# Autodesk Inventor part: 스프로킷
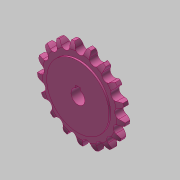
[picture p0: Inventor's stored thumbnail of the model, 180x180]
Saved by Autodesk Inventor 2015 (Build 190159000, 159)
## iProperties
Created: 2019-06
Part Number: 스프로킷
Material: 알루미늄 6061
Document SubType Name: Modeling
Designer: mduedu
Density: 1 g/cm^3
Appearance: 분홍색
Author: mduedu
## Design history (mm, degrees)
sketch "스케치1"
  geometry: L1 (0, 0)-(-3.6, 0); L2 (-3.6, 0)-(-3.6, 32.203); L3 (-2, 38)-(0, 38); L4 (0, 38)-(0, 0); L5 (0, 0)-(3.6, 0); L6 (3.6, 0)-(3.6, 32.203); L7 (2, 38)-(0, 38); A1 r 13.5 centre (9.887, 31.6) between (-2, 38) and (-3.6, 32.203); A2 r 13.5 centre (-9.887, 31.6) between (3.6, 32.203) and (2, 38)
  constraints: 14 end point, 4 point on circle, 4 symmetric about line, 2 centre point, 2 perpendicular, 1 horizontal, 1 parallel, 1 other
  dimensions: "d0" = 76 diameter of L3 L1; "d2" = 7.2 distance between parallel lines of L6 L2; "d3" = 1.6 distance from line of L3.start L2; "d4" = 6.4 distance from line of A2.centre L3; "d5" = 13.5 radius of A1
revolve "회전1" sketch "스케치1" stored, may be unused: angle "d6" = 90 deg
sketch "스케치2"
  geometry: L1 (34.56, 0)-(-34.56, 0); A1 r 34.56 centre (0, 0) between (34.56, 0) and (30.537, -16.182); A2 r 3.975 centre (34.56, 0) between (33.601, 3.858) and (33.601, -3.858); A3 r 12.7 centre (30.537, -16.182) between (37.583, -5.616) and (33.601, -3.858); A4 r 12.7 centre (30.537, 16.182) between (33.601, 3.858) and (37.583, 5.616); A5 r 38 centre (0, 0) between (37.583, -5.616) and (37.583, 5.616); 2 further points
  constraints: 11 point on circle, 5 centre point, 2 coincident, 2 end point, 2 symmetric about line, 1 horizontal, 1 horizontal alignment, 1 tangent, 3 other
  dimensions: "d7" = 69.12 diameter of A1; "d8" = 7.95 diameter of A2; "d9" = 12.7 radius of A3
extrude "돌출1" cut sketch "스케치2" stored distance "d10" = 10; taper "d11" = 0 deg
sketch "스케치3"
  geometry: C1 r 27 at (0, 0); 1 further point
  constraints: 1 centre point, 1 coincident
  dimensions: "d15" = 54 diameter of C1
extrude "돌출2" join sketch "스케치3" stored distance "d16" = 10; taper "d17" = 0 deg
sketch "스케치4"
  geometry: C1 r 11 at (0, 0); 1 further point
  constraints: 1 centre point, 1 coincident
  dimensions: "d18" = 22 diameter of C1
extrude "돌출3" join sketch "스케치4" distance "d19" = 11; taper "d20" = 0 deg
fillet "모깎기1" dims "d21" = 3
sketch "스케치5"
  geometry: L1 (-2, 5.657)-(2, 5.657); L2 (2, 5.657)-(2, 7.8); L3 (2, 7.8)-(-2, 7.8); L4 (-2, 7.8)-(-2, 5.657); A1 r 6 centre (0, 0) between (-2, 5.657) and (2, 5.657); 1 further point
  constraints: 8 end point, 2 parallel, 2 point on circle, 1 centre point, 1 coincident, 1 horizontal, 1 perpendicular
  dimensions: "d24" = 13.8 dimension on A1 L3; "d26" = 4 distance between parallel lines of L2 L4; "d27" = 12 diameter of A1
extrude "돌출4" cut sketch "스케치5" stored distance "d28" = 11; taper "d29" = 0 deg
chamfer "모따기1" distance "d30" = 0.5; stored, may be unused: second distance "d31" = 2, angle "d32" = 45 deg
node "솔리드1"
pattern_circular "원형 패턴1" dims angle "d13" = 360 deg
